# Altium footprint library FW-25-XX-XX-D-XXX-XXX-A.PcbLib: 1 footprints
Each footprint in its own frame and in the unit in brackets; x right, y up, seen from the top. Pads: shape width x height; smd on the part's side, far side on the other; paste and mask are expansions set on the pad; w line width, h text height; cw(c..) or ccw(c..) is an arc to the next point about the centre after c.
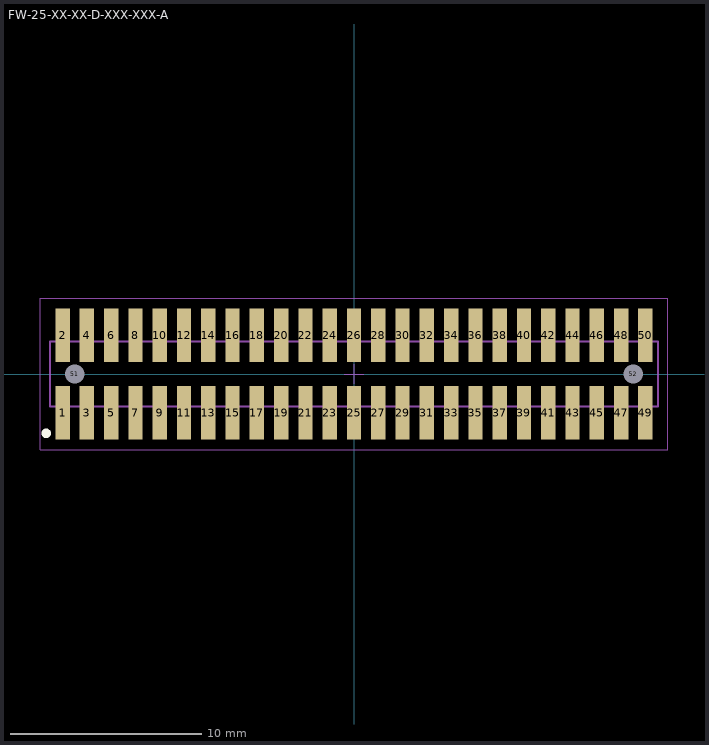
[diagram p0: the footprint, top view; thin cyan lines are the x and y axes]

## FW-25-XX-XX-D-XXX-XXX-A [mm] "1.27mm pitch, 50 pin, board stacker; w/alignment pins, SMT"
height 2.92
pads (52):
  rect 0.75x2.8 smd mask+0: 1(-15.24,-2.032) 2(-15.24,2.032) 3(-13.97,-2.032) 4(-13.97,2.032) 5(-12.7,-2.032) 6(-12.7,2.032) 7(-11.43,-2.032) 8(-11.43,2.032) 9(-10.16,-2.032) 10(-10.16,2.032) 11(-8.89,-2.032) 12(-8.89,2.032) 13(-7.62,-2.032) 14(-7.62,2.032) 15(-6.35,-2.032) 16(-6.35,2.032) 17(-5.08,-2.032) 18(-5.08,2.032) 19(-3.81,-2.032) 20(-3.81,2.032) 21(-2.54,-2.032) 22(-2.54,2.032) 23(-1.27,-2.032) 24(-1.27,2.032) 25(0,-2.032) 26(0,2.032) 27(1.27,-2.032) 28(1.27,2.032) 29(2.54,-2.032) 30(2.54,2.032) 31(3.81,-2.032) 32(3.81,2.032) 33(5.08,-2.032) 34(5.08,2.032) 35(6.35,-2.032) 36(6.35,2.032) 37(7.62,-2.032) 38(7.62,2.032) 39(8.89,-2.032) 40(8.89,2.032) 41(10.16,-2.032) 42(10.16,2.032) 43(11.43,-2.032) 44(11.43,2.032) 45(12.7,-2.032) 46(12.7,2.032) 47(13.97,-2.032) 48(13.97,2.032) 49(15.24,-2.032) 50(15.24,2.032)
  round 0.5 hole 1 unplated mask+0: 51(-14.605,0) 52(14.605,0)
Top Overlay:
  circle w0.25: c-16.1,-3.1 r0.125
Mechanical 12:
  lines w0.001: -15.9,-1.7 -15.9,1.7 15.9,1.7 15.9,-1.7 -15.9,-1.7
Mechanical 13:
  lines w0.1: -15.9,-1.7 -15.9,1.7 15.9,1.7 15.9,-1.7 -15.9,-1.7
  text ".Designator" at 0,0 h1.52
Mechanical 15:
  lines w0.05: -0.5,0 0.5,0 ; 0,-0.5 0,0.5 ; -16.4,-3.95 -16.4,3.95 16.4,3.95 16.4,-3.95 -16.4,-3.95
